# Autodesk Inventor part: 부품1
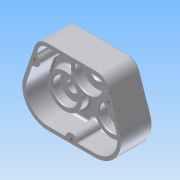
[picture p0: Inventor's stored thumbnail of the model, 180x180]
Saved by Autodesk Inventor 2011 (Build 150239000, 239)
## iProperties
Created: 2014-12
Part Number: 부품1
Document SubType Name: Modeling
Designer: SDA24
Density: 1 g/cm^3
Author: SDA24
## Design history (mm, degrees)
sketch "스케치1"
  geometry: L1 (-47, 36)-(47, 36); L2 (0, 46)-(0, -46); L3 (0, 0)-(-32.527, -32.527); L4 (0, 0)-(32.527, -32.527); L5 (-47, 36)-(-66.565, -20.803); L6 (47, 36)-(66.565, -20.803); L7 (-32.527, -68.527)-(32.527, -68.527); A1 r 46 centre (0, 0) between (0, 46) and (0, -46); A2 r 36 centre (-32.527, -32.527) between (-66.565, -20.803) and (-32.527, -68.527); A3 r 36 centre (32.527, -32.527) between (32.527, -68.527) and (66.565, -20.803); 2 further points
  constraints: 14 end point, 8 point on circle, 4 midpoint, 3 centre point, 3 coincident, 2 horizontal, 2 perpendicular, 2 symmetric about line, 2 tangent, 1 point on line, 1 vertical alignment, 2 other
  dimensions: "d1" = 94 distance of L1.start L1.end; "d2" = 36 distance from line of point (0, 0) L1; "d3" = 92 diameter of A1; "d4" = 90 deg angle of L4 L3 (derived); "d5" = 72 diameter of A2
extrude "돌출1" new body sketch "스케치1" distance "d6" = 44; taper "d7" = 0 deg
fillet "모깎기1" dims "d8" = 18
feature "쉘1" dims "d9" = 5
sketch "스케치2"
  geometry: L1 (-27.675, -53.432)-(-12.291, -8.767) reference; L2 (66.689, -94.527)-(1.635, -94.527) reference; L3 (80.615, -8.767)-(95.999, -53.432) reference; L4 (0, 0)-(68.324, 0) reference; L5 (-27.675, -53.432)-(-12.291, -8.767) reference; L6 (66.689, -94.527)-(1.635, -94.527) reference; L7 (80.615, -8.767)-(95.999, -53.432) reference; L8 (0, 0)-(68.324, 0) reference; A1 r 13 centre (0, -13) between (0, 0) and (-12.291, -8.767) reference; A2 r 31 centre (1.635, -63.527) between (-27.675, -53.432) and (1.635, -94.527) reference; A3 r 31 centre (66.689, -63.527) between (66.689, -94.527) and (95.999, -53.432) reference; A4 r 13 centre (68.324, -13) between (80.615, -8.767) and (68.324, 0) reference; A5 r 13 centre (0, -13) between (0, 0) and (-12.291, -8.767) reference; A6 r 31 centre (1.635, -63.527) between (-27.675, -53.432) and (1.635, -94.527) reference; A7 r 31 centre (66.689, -63.527) between (66.689, -94.527) and (95.999, -53.432) reference; A8 r 13 centre (68.324, -13) between (80.615, -8.767) and (68.324, 0) reference; 1 further point
extrude "돌출2" join sketch "스케치2" distance "d10" = 5; taper "d11" = 0 deg
sketch "스케치3"
  geometry: L1 (66.689, -94.527)-(1.635, -94.527) reference; L2 (0, 5)-(68.324, 5) reference; L3 (80.615, -8.767)-(95.999, -53.432) reference; L4 (34.162, 5)-(34.162, -94.527); L5 (66.689, -94.527)-(1.635, -94.527) reference; L6 (-27.675, -53.432)-(-12.291, -8.767) reference; A1 r 8 centre (85.862, -24) between (83.257, -16.436) and (88.467, -31.564); A2 r 8 centre (34.162, -94.527) between (42.162, -94.527) and (26.162, -94.527); A3 r 8 centre (-17.538, -24) between (-20.143, -31.564) and (-14.933, -16.436); 3 further points
  constraints: 10 point on line, 6 point on circle, 3 centre point, 3 midpoint, 2 end point, 1 coincident, 1 vertical
  dimensions: "d12" = 29 distance from line of L2 point (85.862, -24); "d13" = 16 diameter of A1; "d14" = 29 distance from line of L2 A1.centre; "d15" = 16 diameter of A2; "d16" = 16 diameter of A3; "d17" = 29 distance from line of L2 A3.centre
extrude "돌출3" join sketch "스케치3" distance "d18" = 34; taper "d19" = 0 deg
sketch "스케치4"
  geometry: C1 r 24 at (34.162, -31); C2 r 24 at (1.635, -63.527); C3 r 24 at (66.689, -63.527); A1 r 31 centre (1.635, -63.527) between (-27.675, -53.432) and (1.635, -94.527) reference; A2 r 31 centre (66.689, -63.527) between (66.689, -94.527) and (95.999, -53.432) reference; 1 further point
  constraints: 3 centre point, 3 coincident
  dimensions: "d20" = 48 diameter of C1; "d21" = 48 diameter of C2; "d22" = 48 diameter of C3
extrude "돌출4" join sketch "스케치4" distance "d23" = 11; taper "d24" = 0 deg
sketch "스케치5"
  geometry: C1 r 20 at (-32.527, -32.527); C2 r 20 at (32.527, -32.527); A1 r 36 centre (-32.527, -32.527) between (-66.565, -20.803) and (-32.527, -68.527) reference; A2 r 36 centre (32.527, -32.527) between (32.527, -68.527) and (66.565, -20.803) reference; 1 further point
  constraints: 2 centre point, 2 coincident
  dimensions: "d25" = 40 diameter of C1; "d26" = 40 diameter of C2
extrude "돌출5" join sketch "스케치5" distance "d27" = 7; taper "d28" = -10 deg
sketch "스케치6"
  geometry: C1 r 18.766 at (0, 0) reference; C2 r 15 at (0, 0); 1 further point
  constraints: 1 centre point, 1 coincident
  dimensions: "d29" = 30 diameter of C2
extrude "돌출6" cut sketch "스케치6" distance "d30" = 7; taper "d31" = 0 deg
sketch "스케치7"
  geometry: C1 r 15 at (0, 0) reference; C2 r 7.75 at (0, 0); 1 further point
  constraints: 1 centre point, 1 coincident
  dimensions: "d32" = 15.5 diameter of C2
extrude "돌출7" cut sketch "스케치7" distance "d33" = 10; taper "d34" = 0 deg
sketch "스케치8"
  geometry: C1 r 17.5 at (66.689, -63.527); A1 r 24 centre (66.689, -63.527) between (45.578, -52.111) and (55.273, -42.416) reference
  constraints: 1 centre point, 1 coincident
  dimensions: "d35" = 35 diameter of C1
extrude "돌출8" cut sketch "스케치8" distance "d36" = 11; taper "d37" = 0 deg
sketch "스케치9"
  geometry: C1 r 17.5 at (1.635, -63.527); A1 r 24 centre (1.635, -63.527) between (13.051, -42.416) and (22.746, -52.111) reference
  constraints: 1 centre point, 1 coincident
  dimensions: "d38" = 35 diameter of C1
extrude "돌출9" cut sketch "스케치9" distance "d39" = 11; taper "d40" = 0 deg
sketch "스케치10"
  geometry: C1 r 17.5 at (0, 0) reference; C2 r 7.75 at (0, 0); 1 further point
  constraints: 1 centre point, 1 coincident
  dimensions: "d41" = 15.5 diameter of C2
extrude "돌출10" cut sketch "스케치10" distance "d42" = 10; taper "d43" = 0 deg
sketch "스케치11"
  geometry: C1 r 18.766 at (0, 0) reference; C2 r 15 at (0, 0); 1 further point
  constraints: 1 centre point, 1 coincident
  dimensions: "d44" = 30 diameter of C2
extrude "돌출11" cut sketch "스케치11" distance "d45" = 7; taper "d46" = 0 deg
sketch "스케치12"
  geometry: C1 r 20 at (34.162, -31); A1 r 24 centre (34.162, -31) between (22.746, -52.111) and (45.578, -52.111) reference
  constraints: 1 centre point, 1 coincident
  dimensions: "d47" = 40 diameter of C1
extrude "돌출12" cut sketch "스케치12" distance "d48" = 12; taper "d49" = 0 deg
sketch "스케치13"
  geometry: C1 r 20 at (0, 0) reference; C2 r 10 at (0, 0)
  constraints: 1 centre point, 1 coincident
  dimensions: "d50" = 20 diameter of C2
extrude "돌출13" cut sketch "스케치13" distance "d51" = 3; taper "d52" = 0 deg
chamfer "모따기1" distance "d53" = 1; stored, may be unused: second distance "d54" = 3.175, angle "d55" = 45 deg
fillet "모깎기2" dims "d56" = 3
fillet "모깎기3" dims "d57" = 3
fillet "모깎기4" dims "d58" = 3
fillet "모깎기5" dims "d59" = 3
fillet "모깎기6" dims "d60" = 3
fillet "모깎기7" dims "d61" = 3
fillet "모깎기8" dims "d62" = 0.3
fillet "모깎기9" dims "d63" = 0.1
sketch "스케치14"
  geometry: A1 r 8 centre (51.7, 7) between (47.131, 13.567) and (52.144, -0.988) reference; A2 r 8 centre (0, -63.527) between (7.697, -61.345) and (-7.697, -61.345) reference; A3 r 8 centre (-51.7, 7) between (-52.144, -0.988) and (-47.131, 13.567) reference; 4 further points
  constraints: 3 coincident
hole "Hole1" sketch "스케치14" at (-51.7, 7), (0, -63.527), (51.7, 7) diameter "d64" = 4.1402; stored, may be unused: countersink angle "d68" = 82 deg, drill point angle "d70" = 118 deg; dims "d65" = 20, "d66" = 9.525, "d67" = 6.35, "d69" = 23
node "작업 평면1"
sketch "스케치15"
  geometry: L1 (34.162, 36)-(-34.162, 36) reference; 2 further points
  constraints: 1 vertical alignment, 1 other
  dimensions: "d74" = 30 distance from line of L1 point (0, 6)
feature "엠보싱1" sketch "스케치15" dims "d1" = 94, "d2" = 36, "d3" = 92, "d4" = 90 deg (derived), "d5" = 72, "d65" = 20, "d75" = 1, "d76" = 0
fillet "모깎기10" dims "d77" = 0.3
node "솔리드1"
node "투영된 루프1"
other parameters: "d71" = -33.3375
